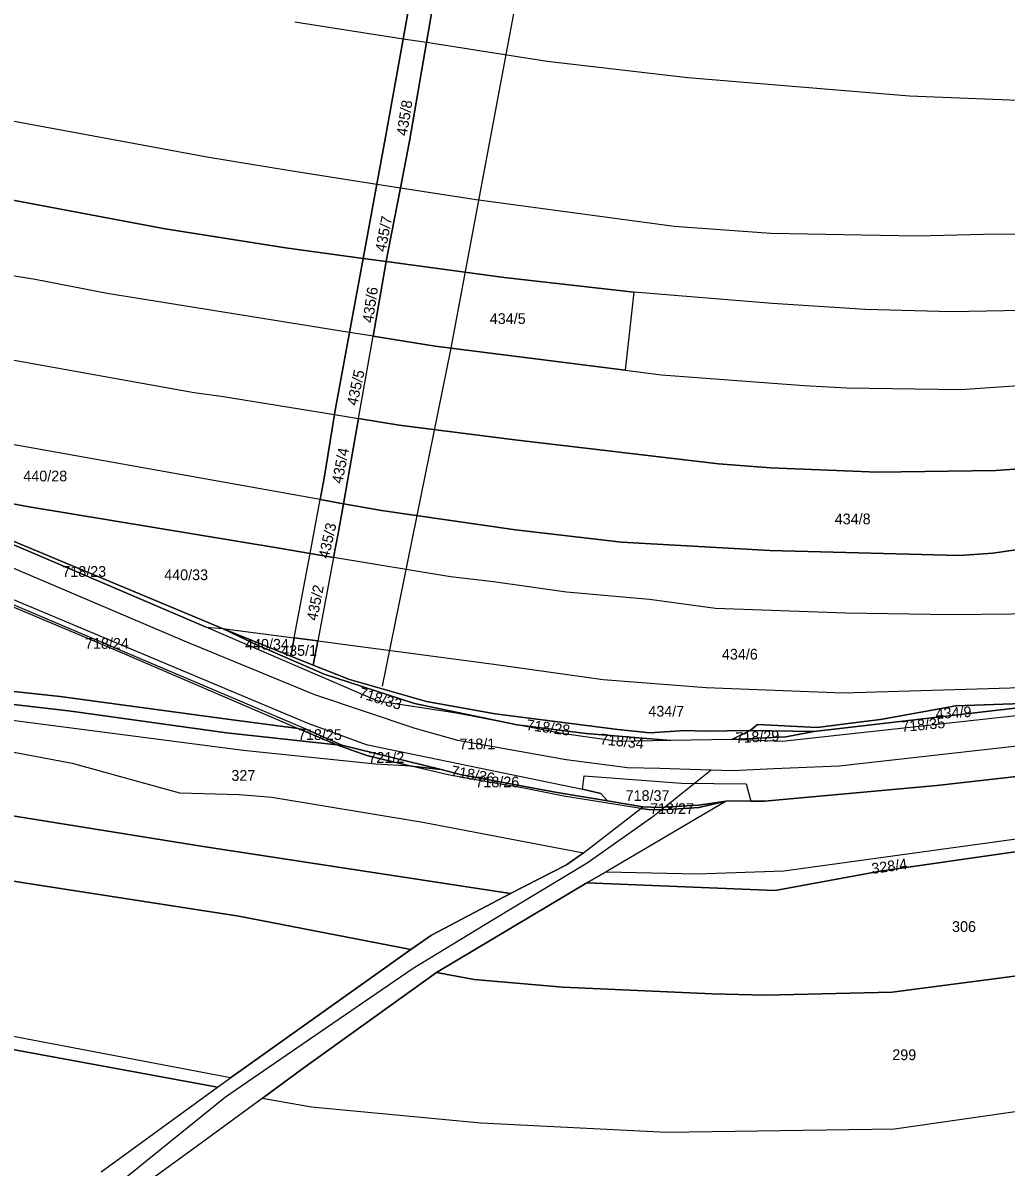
# Model space of a CAD drawing. Extents: x -629983 to -626385, y -1072828 to -1067897.
# Drawn here: x -628378.9 to -628103.8, y -1070963.6 to -1070643.4 of the extents above; entities that cross this region are included whole.
import ezdxf

# ---------------------------------------------------------------- set-up
doc = ezdxf.new("R2010")
doc.units = 0
for name, color, linetype in [('Cesty', 7, 'Continuous'), ('Parcela nároku', 7, 'Continuous'), ('Parcelní číslo', 7, 'Continuous'), ('silnice III třídy', 7, 'Continuous'), ('Silnice ŘSD', 7, 'Continuous')]:
    doc.layers.add(name, color=color, linetype=linetype)

msp = doc.modelspace()

# ---------------------------------------------------------------- linework, layer by layer
at = {"layer": 'Cesty'}
msp.add_lwpolyline([(-628278.28, -1070828.99), (-628259.19, -1070734.89), (-628220.88, -1070530.25), (-628148.19, -1070051.86), (-628124.88, -1069886.45), (-628121.14, -1069861.86), (-628117.17, -1069852.4), (-628107.82, -1069847.56)], dxfattribs=at)
at = {"layer": 'Parcela nároku'}
for points in [[(-628272.51, -1070647.92), (-628266.51, -1070614.38), (-628266.12, -1070612.44), (-628259.61, -1070613.49), (-628263.64, -1070635.31), (-628265.99, -1070648.94)], [(-628265.99, -1070648.94), (-628272.51, -1070647.92), (-628277.43, -1070675.4), (-628279.84, -1070688.5), (-628273.28, -1070689.52), (-628270.74, -1070676.48)], [(-628602.19, -1070666.96), (-628548.71, -1070655.21), (-628531.23, -1070652.93), (-628510.74, -1070653.19), (-628492.1, -1070654.2), (-628459.72, -1070657.48), (-628388.99, -1070669.47), (-628326.86, -1070680.98), (-628304.09, -1070684.71), (-628279.84, -1070688.5), (-628283.67, -1070709.31), (-628305.46, -1070706.37), (-628339.07, -1070701.03), (-628427.29, -1070684.39), (-628481.36, -1070677.66), (-628516.29, -1070675.93), (-628522.67, -1070675.22), (-628550.98, -1070675.45), (-628562.54, -1070676.23), (-628572.12, -1070677.47), (-628588.73, -1070680.39), (-628619.98, -1070686.64), (-628644.08, -1070676.46)], [(-628522.67, -1070675.22), (-628516.29, -1070675.93), (-628481.36, -1070677.66), (-628427.29, -1070684.39), (-628339.07, -1070701.03), (-628305.46, -1070706.37), (-628283.67, -1070709.31), (-628287.49, -1070730.03), (-628355.28, -1070719.1), (-628375.46, -1070715.21), (-628410.31, -1070709.65), (-628470.38, -1070699.5), (-628491.21, -1070696.81), (-628522.9, -1070695.33), (-628549.68, -1070695.51), (-628588.04, -1070700.17), (-628619.98, -1070686.64), (-628588.73, -1070680.39), (-628572.12, -1070677.47), (-628562.54, -1070676.23), (-628550.98, -1070675.45)], [(-628283.67, -1070709.31), (-628279.84, -1070688.5), (-628273.28, -1070689.52), (-628276.73, -1070707.23), (-628277.25, -1070710.18)], [(-628355.28, -1070719.1), (-628375.46, -1070715.21), (-628410.31, -1070709.65), (-628470.38, -1070699.5), (-628491.21, -1070696.81), (-628522.9, -1070695.33), (-628549.68, -1070695.51), (-628588.04, -1070700.17), (-628572.14, -1070706.7), (-628549.66, -1070716.91), (-628546.08, -1070718.46), (-628507.25, -1070718.49), (-628481.78, -1070721.37), (-628421.88, -1070730.5), (-628331, -1070746.84), (-628323.39, -1070747.88), (-628291.69, -1070753.03), (-628291.41, -1070751.33), (-628287.49, -1070730.03)], [(-628089.53, -1070723.69), (-628119.2, -1070724.29), (-628143.14, -1070723.63), (-628169.3, -1070721.91), (-628208.02, -1070718.77), (-628210.4, -1070740.59), (-628200.21, -1070741.84), (-628160.37, -1070744.83), (-628148.47, -1070745.57), (-628116.56, -1070746.01), (-628089.45, -1070744.15), (-628011.54, -1070738.64), (-627997, -1070736.78), (-627949.38, -1070732.03), (-627913.55, -1070729.01), (-627881.94, -1070725.77), (-627827.95, -1070719.34), (-627825.9, -1070701.23), (-627853.73, -1070701.79), (-627880.72, -1070703.61), (-627913.59, -1070710.23), (-627936.72, -1070712.94), (-627967.91, -1070715.76), (-628030.92, -1070720.12)], [(-628287.49, -1070730.03), (-628283.67, -1070709.31), (-628277.25, -1070710.18), (-628280.94, -1070731.09)], [(-628244.23, -1070714.64), (-628208.02, -1070718.77), (-628210.4, -1070740.59), (-628263.51, -1070733.9), (-628280.94, -1070731.09), (-628277.25, -1070710.18)], [(-628421.88, -1070730.5), (-628331, -1070746.84), (-628323.39, -1070747.88), (-628291.69, -1070753.03), (-628294.58, -1070770.79), (-628295.71, -1070776.8), (-628383.33, -1070761.08), (-628411.49, -1070755.61), (-628489.63, -1070742.36), (-628521.56, -1070728.54), (-628546.08, -1070718.46), (-628507.25, -1070718.49), (-628481.78, -1070721.37)], [(-628280.94, -1070731.09), (-628287.49, -1070730.03), (-628291.41, -1070751.33), (-628291.69, -1070753.03), (-628285.01, -1070754.12)], [(-628411.49, -1070755.61), (-628489.63, -1070742.36), (-628465.03, -1070752.27), (-628427.22, -1070769.41), (-628377.73, -1070778.75), (-628306.59, -1070790.51), (-628298.54, -1070791.86), (-628295.71, -1070776.8), (-628383.33, -1070761.08)], [(-628291.69, -1070753.03), (-628285.01, -1070754.12), (-628289.22, -1070777.96), (-628295.71, -1070776.8), (-628294.58, -1070770.79)], [(-628010.48, -1070761.71), (-628009.29, -1070779.27), (-628023.62, -1070780.61), (-628072.18, -1070786.65), (-628107.59, -1070791.76), (-628116.86, -1070792.47), (-628169.95, -1070791.05), (-628211.46, -1070788.71), (-628241.06, -1070785.3), (-628278.54, -1070779.88), (-628289.22, -1070777.96), (-628285.01, -1070754.12), (-628273.61, -1070755.97), (-628241.28, -1070760.05), (-628184.29, -1070766.78), (-628169.73, -1070767.9), (-628139.79, -1070769.1), (-628106.74, -1070768.7)], [(-628491.52, -1070759.67), (-628495.21, -1070759.45), (-628441.1, -1070782.41), (-628416.98, -1070791.82), (-628393.75, -1070801.73), (-628354.38, -1070818.31), (-628301.91, -1070840.84), (-628299.45, -1070841.11), (-628393.92, -1070800.99)], [(-628427.22, -1070769.41), (-628429.24, -1070769.05), (-628327.59, -1070812.45), (-628323.01, -1070812.85)], [(-628298.54, -1070791.86), (-628306.59, -1070790.51), (-628377.73, -1070778.75), (-628427.22, -1070769.41), (-628323.01, -1070812.85), (-628302.97, -1070815.48)], [(-628298.54, -1070791.86), (-628295.71, -1070776.8), (-628289.22, -1070777.96), (-628290.69, -1070786.26), (-628291.95, -1070792.96)], [(-628302.97, -1070815.48), (-628298.54, -1070791.86), (-628291.95, -1070792.96), (-628296.36, -1070816.35)], [(-628247.27, -1070799.8), (-628259.3, -1070798.44), (-628291.95, -1070792.96), (-628296.36, -1070816.35), (-628247.12, -1070822.81), (-628216.56, -1070827.1), (-628187.75, -1070829.4), (-628149.38, -1070830.85), (-628083.99, -1070828.93), (-628074.3, -1070806.42), (-628093.93, -1070808.73), (-628119.22, -1070809.04), (-628148.65, -1070808.59), (-628185.16, -1070807.29), (-628203.61, -1070804.75), (-628226.8, -1070802.73)], [(-628323.01, -1070812.85), (-628314.13, -1070817.11), (-628294.64, -1070825.61), (-628269.31, -1070833.84), (-628240.58, -1070839.85), (-628257.57, -1070836.59), (-628279.58, -1070833.2), (-628327.59, -1070812.45)], [(-628457.52, -1070822.75), (-628440.2, -1070824.12), (-628368.44, -1070831.88), (-628323.05, -1070838.07), (-628301.91, -1070840.84), (-628291.06, -1070845.46), (-628321.93, -1070842.1), (-628366.1, -1070835.92), (-628455.22, -1070825.61), (-628473.82, -1070823.92), (-628479.39, -1070823.18), (-628534.91, -1070817.69), (-628536.84, -1070814.78), (-628478.2, -1070820.5)], [(-628323.01, -1070812.85), (-628302.97, -1070815.48), (-628303.94, -1070820.64)], [(-628303.94, -1070820.64), (-628297.64, -1070823.15), (-628287.56, -1070827.16), (-628265.95, -1070833.25), (-628246.75, -1070836.76), (-628212.49, -1070841.12), (-628203.49, -1070842.04), (-628193.58, -1070841.42), (-628188.29, -1070841.57), (-628175.41, -1070841.4), (-628180.6, -1070843.91), (-628197.6, -1070844.22), (-628221.35, -1070842.27), (-628240.58, -1070839.85), (-628269.31, -1070833.84), (-628294.64, -1070825.61), (-628314.13, -1070817.11), (-628323.01, -1070812.85)], [(-628302.97, -1070815.48), (-628296.36, -1070816.35), (-628297.64, -1070823.15), (-628303.94, -1070820.64)], [(-627886.52, -1070812.71), (-627886.24, -1070814.04), (-627928.69, -1070817.68), (-627986.6, -1070823.2), (-628019.88, -1070827.58), (-628101.01, -1070837.33), (-628160.56, -1070843.84), (-628166.52, -1070844.44), (-628180.6, -1070843.91), (-628165.45, -1070843.15), (-628157.61, -1070841.67), (-628086.12, -1070833.36), (-628015.19, -1070825.26), (-627988.85, -1070821.87), (-627936.08, -1070816.85), (-627933.12, -1070816.63), (-627913.43, -1070815.14)], [(-628247.12, -1070822.81), (-628216.56, -1070827.1), (-628187.75, -1070829.4), (-628149.38, -1070830.85), (-628083.99, -1070828.93), (-628086.12, -1070833.36), (-628117.9, -1070834.54), (-628138.98, -1070838.36), (-628147.23, -1070839.37), (-628156.65, -1070840.55), (-628173.41, -1070839.76), (-628175.41, -1070841.4), (-628188.29, -1070841.57), (-628193.58, -1070841.42), (-628203.49, -1070842.04), (-628212.49, -1070841.12), (-628246.75, -1070836.76), (-628265.95, -1070833.25), (-628287.56, -1070827.16), (-628297.64, -1070823.15), (-628296.36, -1070816.35)], [(-628452.18, -1070834.12), (-628365.1, -1070850.56), (-628335.08, -1070858.89), (-628318.42, -1070859.27), (-628309.27, -1070860.04), (-628266.98, -1070867.09), (-628222.04, -1070875.61), (-628226.8, -1070879.04), (-628242.47, -1070886.99), (-628328.41, -1070873.88), (-628474.52, -1070850.34), (-628512.02, -1070844.32), (-628538.6, -1070840.92), (-628536.2, -1070820.59), (-628501.83, -1070824.52), (-628500.04, -1070825.3), (-628461.34, -1070832.48)], [(-628414.76, -1070834.87), (-628501.83, -1070824.52), (-628500.04, -1070825.3), (-628461.34, -1070832.48), (-628452.18, -1070834.12), (-628365.1, -1070850.56), (-628335.08, -1070858.89), (-628318.42, -1070859.27), (-628309.27, -1070860.04), (-628266.98, -1070867.09), (-628222.04, -1070875.61), (-628206.05, -1070863.23), (-628210.65, -1070862.51), (-628227.53, -1070859.76), (-628239.26, -1070857.44), (-628250.22, -1070855.62), (-628259.95, -1070853.79), (-628270.3, -1070851.38), (-628280.29, -1070850.81), (-628317.24, -1070847.05), (-628382.54, -1070838.49), (-628396.29, -1070837.55)], [(-628175.41, -1070841.4), (-628173.41, -1070839.76), (-628156.65, -1070840.55), (-628147.23, -1070839.37), (-628138.98, -1070838.36), (-628117.9, -1070834.54), (-628086.12, -1070833.36), (-628157.61, -1070841.67)], [(-628299.45, -1070841.11), (-628289.62, -1070845.49), (-628291.06, -1070845.46), (-628301.91, -1070840.84)], [(-628240.58, -1070839.85), (-628221.35, -1070842.27), (-628197.6, -1070844.22), (-628212.49, -1070844.5), (-628228.13, -1070842.24)], [(-628171.38, -1070861.19), (-628175.29, -1070861.2), (-628182.16, -1070861.21), (-628215.75, -1070880.91), (-628190.3, -1070881.53), (-628166.04, -1070880.67), (-628063.03, -1070866.47), (-628056.23, -1070868.75), (-628007.41, -1070855.92), (-627987.49, -1070849.7), (-627990.17, -1070845.69), (-628000.36, -1070842.17), (-628077, -1070851.61), (-628123.2, -1070856.79)], [(-628175.41, -1070841.4), (-628157.61, -1070841.67), (-628165.45, -1070843.15), (-628180.6, -1070843.91)], [(-628291.06, -1070845.46), (-628289.62, -1070845.49), (-628261.83, -1070852.36), (-628270.3, -1070851.38), (-628282.67, -1070848.44)], [(-628215.34, -1070861.08), (-628205.44, -1070862.74), (-628206.05, -1070863.23), (-628210.65, -1070862.51), (-628227.53, -1070859.76), (-628239.26, -1070857.44), (-628250.22, -1070855.62), (-628259.95, -1070853.79), (-628270.3, -1070851.38), (-628261.83, -1070852.36), (-628256.57, -1070853.73), (-628229.46, -1070858.72)], [(-628221.85, -1070854.1), (-628194.61, -1070856.11), (-628176.53, -1070856.34), (-628175.29, -1070861.2), (-628182.16, -1070861.21), (-628189.91, -1070862.33), (-628200.98, -1070862.98), (-628205.44, -1070862.74), (-628215.34, -1070861.08), (-628217.19, -1070859.06), (-628222.34, -1070857.83)], [(-628005.42, -1070860.68), (-627991.64, -1070860.27), (-627987.41, -1070874.59), (-627992.36, -1070890.28), (-627999.17, -1070892.22), (-628036.55, -1070898.1), (-628091.52, -1070908.87), (-628135.68, -1070914.66), (-628171.14, -1070915.49), (-628186.02, -1070915.12), (-628227.81, -1070913.26), (-628252.66, -1070911.12), (-628263.14, -1070909.11), (-628221.13, -1070884.07), (-628168.4, -1070886.19), (-628139.07, -1070880.8), (-628064.22, -1070870.06), (-628053.62, -1070874.59), (-628019.31, -1070869.99)], [(-628200.98, -1070862.98), (-628189.91, -1070862.33), (-628182.16, -1070861.21), (-628189.76, -1070862.93), (-628198.3, -1070863.48), (-628203.19, -1070863.63), (-628206.05, -1070863.23), (-628205.44, -1070862.74)], [(-628166.04, -1070880.67), (-628063.03, -1070866.47), (-628056.23, -1070868.75), (-628064.22, -1070870.06), (-628139.07, -1070880.8), (-628168.4, -1070886.19), (-628221.13, -1070884.07), (-628215.75, -1070880.91), (-628190.3, -1070881.53)], [(-628227.81, -1070913.26), (-628186.02, -1070915.12), (-628171.14, -1070915.49), (-628135.68, -1070914.66), (-628091.52, -1070908.87), (-628036.55, -1070898.1), (-627999.17, -1070892.22), (-627992.36, -1070890.28), (-627998.03, -1070902.28), (-627995.58, -1070929.26), (-628030.61, -1070935.24), (-628078.59, -1070944.87), (-628135.03, -1070952.93), (-628198.8, -1070953.87), (-628250.8, -1070951.29), (-628298.12, -1070946.76), (-628311.98, -1070944.35), (-628300.59, -1070936.02), (-628263.14, -1070909.11), (-628252.66, -1070911.12)], [(-628331.46, -1070958.61), (-628354.57, -1070975.46), (-628250.75, -1070992.75), (-628210.59, -1070996.63), (-628170.63, -1070998.53), (-628137.42, -1070996.44), (-628108.15, -1070991.5), (-628036.8, -1070976.12), (-628000.12, -1070970.48), (-627993.94, -1070968.01), (-627988.33, -1070964.81), (-627986.83, -1070952.94), (-627984.18, -1070921.67), (-627995.58, -1070929.26), (-628030.61, -1070935.24), (-628078.59, -1070944.87), (-628135.03, -1070952.93), (-628198.8, -1070953.87), (-628250.8, -1070951.29), (-628298.12, -1070946.76), (-628311.98, -1070944.35)]]:
    msp.add_lwpolyline(points, close=True, dxfattribs=at)
for points in [[(-627903.25, -1070656.94), (-627969.61, -1070662.08), (-628010.4, -1070663.68), (-628050.69, -1070664.96), (-628095.77, -1070665.28), (-628130.82, -1070663.87), (-628192.91, -1070658.82), (-628232.19, -1070654.23), (-628265.99, -1070648.94), (-628263.64, -1070635.31), (-628259.61, -1070613.49), (-628222.19, -1070619.55), (-628170.37, -1070625.67), (-628130.69, -1070628.69), (-628086.68, -1070632.01), (-628060.6, -1070633.22), (-628020.49, -1070633.87), (-627969.04, -1070632.64), (-627947.86, -1070631.28), (-627921.14, -1070630.03), (-627870.01, -1070625.59)], [(-628266.51, -1070614.38), (-628272.51, -1070647.92), (-628302.84, -1070643.17)], [(-628806.74, -1070625.37), (-628693.42, -1070673.79), (-628643.05, -1070694.92), (-628550.51, -1070733.05), (-628487.8, -1070759.97), (-628390.08, -1070801.2), (-628299.13, -1070839.37), (-628282.87, -1070845.37), (-628222.34, -1070857.83), (-628221.85, -1070854.1), (-628194.61, -1070856.11), (-628176.53, -1070856.34), (-628175.29, -1070861.2), (-628171.38, -1070861.19), (-628123.2, -1070856.79), (-628077, -1070851.61), (-628000.36, -1070842.17), (-628002.78, -1070841.25), (-627960.57, -1070836.87), (-627945.52, -1070835.28), (-627932.44, -1070834.08), (-627845.93, -1070825.43)], [(-628651.77, -1070635.89), (-628709.71, -1070648.87), (-628687.35, -1070657.95), (-628644.08, -1070676.46), (-628602.19, -1070666.96), (-628548.71, -1070655.21), (-628531.23, -1070652.93), (-628510.74, -1070653.19), (-628492.1, -1070654.2), (-628459.72, -1070657.48), (-628388.99, -1070669.47), (-628326.86, -1070680.98), (-628304.09, -1070684.71), (-628279.84, -1070688.5), (-628277.43, -1070675.4), (-628272.51, -1070647.92), (-628302.84, -1070643.17)], [(-627903.25, -1070656.94), (-627969.61, -1070662.08), (-628010.4, -1070663.68), (-628050.69, -1070664.96), (-628095.77, -1070665.28), (-628130.82, -1070663.87), (-628192.91, -1070658.82), (-628232.19, -1070654.23), (-628265.99, -1070648.94), (-628270.74, -1070676.48), (-628273.28, -1070689.52), (-628252.05, -1070692.84), (-628196.68, -1070700.32), (-628169.65, -1070702.28), (-628128.71, -1070703.03), (-628110.17, -1070702.51), (-628061.9, -1070702.16), (-628000.02, -1070700.46), (-627945.67, -1070697.4), (-627911.39, -1070694.75), (-627878.35, -1070689.15)], [(-627880.72, -1070703.61), (-627913.59, -1070710.23), (-627936.72, -1070712.94), (-627967.91, -1070715.76), (-628030.92, -1070720.12), (-628089.53, -1070723.69), (-628119.2, -1070724.29), (-628143.14, -1070723.63), (-628169.3, -1070721.91), (-628208.02, -1070718.77), (-628244.23, -1070714.64), (-628277.25, -1070710.18), (-628276.73, -1070707.23), (-628273.28, -1070689.52), (-628252.05, -1070692.84), (-628196.68, -1070700.32), (-628169.65, -1070702.28), (-628128.71, -1070703.03), (-628110.17, -1070702.51), (-628061.9, -1070702.16), (-628000.02, -1070700.46), (-627945.67, -1070697.4), (-627911.39, -1070694.75), (-627878.35, -1070689.15)], [(-627910.01, -1070754.54), (-627980.13, -1070759.5), (-628010.48, -1070761.71), (-628106.74, -1070768.7), (-628139.79, -1070769.1), (-628169.73, -1070767.9), (-628184.29, -1070766.78), (-628241.28, -1070760.05), (-628273.61, -1070755.97), (-628285.01, -1070754.12), (-628280.94, -1070731.09), (-628263.51, -1070733.9), (-628210.4, -1070740.59), (-628200.21, -1070741.84), (-628160.37, -1070744.83), (-628148.47, -1070745.57), (-628116.56, -1070746.01), (-628089.45, -1070744.15), (-628011.54, -1070738.64), (-627997, -1070736.78), (-627949.38, -1070732.03), (-627913.55, -1070729.01), (-627881.94, -1070725.77)], [(-627886.24, -1070814.04), (-627928.69, -1070817.68), (-627986.6, -1070823.2), (-628019.88, -1070827.58), (-628101.01, -1070837.33), (-628160.56, -1070843.84), (-628166.52, -1070844.44), (-628180.6, -1070843.91), (-628197.6, -1070844.22), (-628212.49, -1070844.5), (-628228.13, -1070842.24), (-628240.58, -1070839.85), (-628257.57, -1070836.59), (-628279.58, -1070833.2), (-628327.59, -1070812.45), (-628429.24, -1070769.05)], [(-628093.93, -1070808.73), (-628119.22, -1070809.04), (-628148.65, -1070808.59), (-628185.16, -1070807.29), (-628203.61, -1070804.75), (-628226.8, -1070802.73), (-628247.27, -1070799.8), (-628259.3, -1070798.44), (-628291.95, -1070792.96), (-628290.69, -1070786.26), (-628289.22, -1070777.96), (-628278.54, -1070779.88), (-628241.06, -1070785.3), (-628211.46, -1070788.71), (-628169.95, -1070791.05), (-628116.86, -1070792.47), (-628107.59, -1070791.76), (-628072.18, -1070786.65)], [(-628393.75, -1070801.73), (-628354.38, -1070818.31), (-628301.91, -1070840.84), (-628323.05, -1070838.07), (-628368.44, -1070831.88), (-628440.2, -1070824.12)], [(-628390.08, -1070801.2), (-628299.13, -1070839.37), (-628282.87, -1070845.37), (-628222.34, -1070857.83), (-628217.19, -1070859.06), (-628215.34, -1070861.08), (-628229.46, -1070858.72), (-628256.57, -1070853.73), (-628261.83, -1070852.36), (-628289.62, -1070845.49), (-628299.45, -1070841.11), (-628393.92, -1070800.99)], [(-628455.22, -1070825.61), (-628366.1, -1070835.92), (-628321.93, -1070842.1), (-628291.06, -1070845.46), (-628282.67, -1070848.44), (-628270.3, -1070851.38), (-628280.29, -1070850.81), (-628317.24, -1070847.05), (-628382.54, -1070838.49)], [(-628474.52, -1070850.34), (-628328.41, -1070873.88), (-628242.47, -1070886.99), (-628264.54, -1070898.68), (-628270.37, -1070902.66), (-628318.46, -1070893.37), (-628417.13, -1070878.06)], [(-628357.03, -1070964.86), (-628324.42, -1070941.18), (-628320.82, -1070938.58), (-628270.37, -1070902.66), (-628264.54, -1070898.68), (-628242.47, -1070886.99), (-628226.8, -1070879.04), (-628222.04, -1070875.61), (-628206.05, -1070863.23), (-628203.19, -1070863.63), (-628198.3, -1070863.48), (-628189.76, -1070862.93), (-628182.16, -1070861.21), (-628215.75, -1070880.91), (-628221.13, -1070884.07), (-628263.14, -1070909.11), (-628300.59, -1070936.02), (-628311.98, -1070944.35), (-628331.46, -1070958.61), (-628354.57, -1070975.46)], [(-628417.13, -1070878.06), (-628318.46, -1070893.37), (-628270.37, -1070902.66), (-628320.82, -1070938.58), (-628391.5, -1070925.19)], [(-628781.86, -1070986.24), (-628696.9, -1070948.55), (-628671.44, -1070938.84), (-628628.48, -1070923.55), (-628602.77, -1070915.65), (-628585.16, -1070911.63), (-628553.52, -1070907.62), (-628531.29, -1070906.78), (-628510.62, -1070909.12), (-628455.75, -1070917.07), (-628324.42, -1070941.18), (-628320.82, -1070938.58), (-628391.5, -1070925.19), (-628490.51, -1070908.74), (-628515.29, -1070905.61), (-628538.83, -1070903.72), (-628562.42, -1070905.84), (-628592.03, -1070910.52), (-628609.91, -1070914.99), (-628625.85, -1070920.13), (-628672.98, -1070936.41), (-628713.88, -1070952.86), (-628846.18, -1071010.81)], [(-628357.03, -1070964.86), (-628324.42, -1070941.18), (-628455.75, -1070917.07), (-628510.62, -1070909.12), (-628531.29, -1070906.78), (-628553.52, -1070907.62), (-628585.16, -1070911.63), (-628602.77, -1070915.65), (-628628.48, -1070923.55), (-628671.44, -1070938.84), (-628696.9, -1070948.55), (-628781.86, -1070986.24)]]:
    msp.add_lwpolyline(points, dxfattribs=at)
at = {"layer": 'silnice III třídy'}
msp.add_lwpolyline([(-628186.34, -1070852.47), (-628186.34, -1070852.47), (-628202.66, -1070865.58), (-628221.03, -1070878.55), (-628247.3, -1070894.43), (-628269.72, -1070907.98), (-628300.75, -1070929.27), (-628322.2, -1070943.99), (-628353.36, -1070969.18)], dxfattribs=at)
at = {"layer": 'Silnice ŘSD'}
for p, q in [((-628333.69, -1070816.42), (-628419.89, -1070779.67)), ((-628297.2, -1070831.47), (-628333.69, -1070816.42)), ((-628269.11, -1070840.88), (-628297.2, -1070831.47)), ((-628257.25, -1070844.19), (-628269.11, -1070840.88)), ((-628226.92, -1070849.64), (-628257.25, -1070844.19)), ((-628087.5, -1070844.24), (-628119, -1070847.8)), ((-628209.74, -1070851.83), (-628226.92, -1070849.64)), ((-628119, -1070847.8), (-628150.5, -1070851.36)), ((-628200.72, -1070852.08), (-628209.74, -1070851.83)), ((-628168.86, -1070852.15), (-628180.38, -1070852.65)), ((-628150.5, -1070851.36), (-628168.86, -1070852.15))]:
    msp.add_line(p, q, dxfattribs=at)
msp.add_lwpolyline([(-628180.38, -1070852.65), (-628192.29, -1070852.32), (-628200.72, -1070852.08)], dxfattribs=at)

# ---------------------------------------------------------------- texts
at = {"layer": 'Parcelní číslo'}
for s, rotation, p in [('435/8', 80.8205, (-628271.47, -1070675.19)), ('435/7', 79.1145, (-628277.46, -1070707.65)), ('435/6', 81.7496, (-628280.97, -1070727.46)), ('435/5', 77.8249, (-628285.38, -1070750.67)), ('435/4', 78.9651, (-628289.55, -1070772.5)), ('435/3', 77.2109, (-628293.35, -1070793.51)), ('435/2', 78.9705, (-628296.59, -1070810.86)), ('718/33', 343.0235, (-628285.22, -1070832.09)), ('434/9', 3.2625, (-628123.46, -1070838.19)), ('718/35', 5.4959, (-628133, -1070841.85)), ('718/28', 352.3161, (-628238.2, -1070841.24)), ('718/29', 3.1242, (-628179.45, -1070844.97)), ('718/34', 353.6557, (-628217.54, -1070845.23)), ('718/36', 349.6886, (-628259.31, -1070854.11)), ('328/4', 7.8587, (-628141.28, -1070881.55))]:
    msp.add_text(s, height=3, rotation=rotation, dxfattribs=at).set_placement(p)
for s, p in [('434/5', (-628248.27, -1070727.66)), ('440/28', (-628378.76, -1070771.7)), ('434/8', (-628151.77, -1070783.7)), ('718/23', (-628367.86, -1070798.41)), ('440/33', (-628339.35, -1070799.34)), ('718/24', (-628361.51, -1070818.54)), ('440/34', (-628316.73, -1070818.79)), ('435/1', (-628306.63, -1070820.52)), ('434/6', (-628183.34, -1070821.57)), ('434/7', (-628203.93, -1070837.51)), ('718/25', (-628301.93, -1070844.05)), ('718/1', (-628256.79, -1070846.66)), ('721/2', (-628282.23, -1070850.46)), ('327', (-628320.55, -1070855.49)), ('718/26', (-628252.3, -1070857.3)), ('718/37', (-628210.28, -1070861.12)), ('718/27', (-628203.44, -1070864.77)), ('306', (-628118.95, -1070897.77)), ('299', (-628135.68, -1070933.65))]:
    msp.add_text(s, height=3, dxfattribs=at).set_placement(p)

doc.saveas('drawing.dxf')
